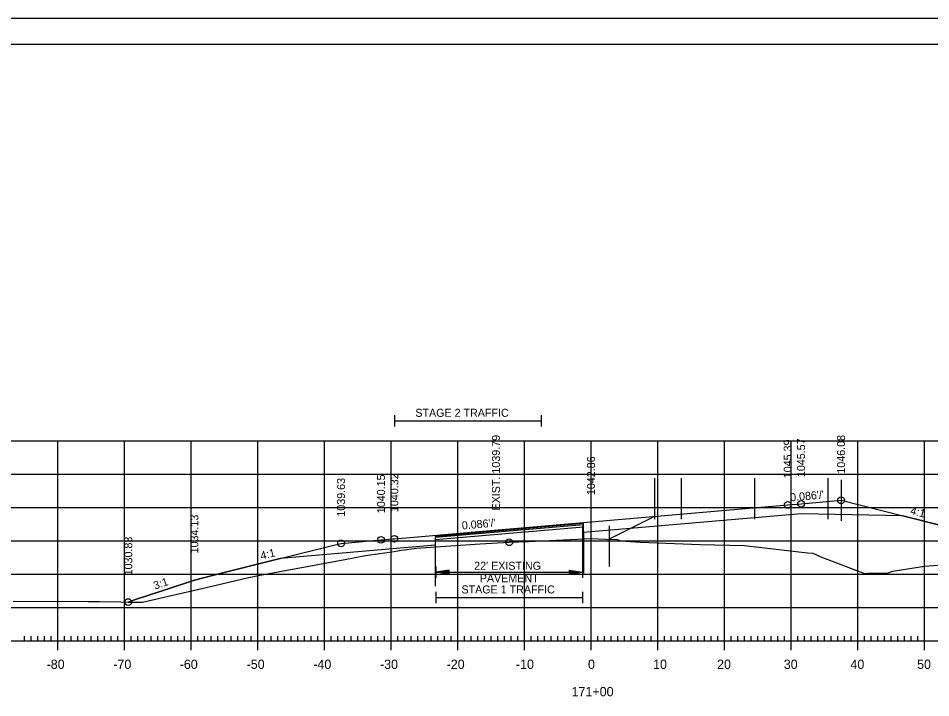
# Model space of a CAD drawing. Extents: x 1322838 to 1324533, y 339903 to 351025.
# Drawn here: x 1323617.8 to 1323754.7, y 347083.3 to 347185.2 of the extents above; entities that cross this region are included whole.
import ezdxf

# ---------------------------------------------------------------- set-up
doc = ezdxf.new("R2010")
doc.units = 0
for name, color, linetype in [('R_Alt Surface', 7, 'Continuous'), ('R_Axis', 7, 'Continuous'), ('R_Axis Annot', 7, 'Continuous'), ('R_Border', 7, 'Continuous'), ('R_Exist Surface', 7, 'Continuous'), ('R_Fin Surface', 7, 'Continuous'), ('R_Fin Surface Annot', 7, 'Continuous'), ('R_Grid', 7, 'Continuous'), ('R_No Plot', 7, 'Continuous'), ('R_Xsect Elev', 7, 'Continuous')]:
    doc.layers.add(name, color=color, linetype=linetype)

msp = doc.modelspace()

# ---------------------------------------------------------------- linework, layer by layer
at = {"layer": 'R_Alt Surface'}
msp.add_lwpolyline([(1323750.5, 347110.6), (1323735.22, 347110.9), (1323703.72, 347108.2), (1323702.59, 347108.09), (1323702.58, 347109.43), (1323680.34, 347107.52), (1323680.33, 347106.18), (1323672.22, 347105.49), (1323657.07, 347104.18)], dxfattribs=at)
at = {"layer": 'R_Axis'}
for p, q in [((1323618.72, 347091.84), (1323618.72, 347092.54)), ((1323619.72, 347091.84), (1323619.72, 347092.54)), ((1323620.72, 347091.84), (1323620.72, 347092.54)), ((1323621.72, 347091.84), (1323621.72, 347092.54)), ((1323622.72, 347091.84), (1323622.72, 347092.54)), ((1323623.72, 347090.44), (1323623.72, 347093.24)), ((1323624.72, 347091.84), (1323624.72, 347092.54)), ((1323625.72, 347091.84), (1323625.72, 347092.54)), ((1323626.72, 347091.84), (1323626.72, 347092.54)), ((1323627.72, 347091.84), (1323627.72, 347092.54)), ((1323628.72, 347091.84), (1323628.72, 347092.54)), ((1323629.72, 347091.84), (1323629.72, 347092.54)), ((1323630.72, 347091.84), (1323630.72, 347092.54)), ((1323631.72, 347091.84), (1323631.72, 347092.54)), ((1323632.72, 347091.84), (1323632.72, 347092.54)), ((1323633.72, 347090.44), (1323633.72, 347093.24)), ((1323634.72, 347091.84), (1323634.72, 347092.54)), ((1323635.72, 347091.84), (1323635.72, 347092.54)), ((1323636.72, 347091.84), (1323636.72, 347092.54)), ((1323637.72, 347091.84), (1323637.72, 347092.54)), ((1323638.72, 347091.84), (1323638.72, 347092.54)), ((1323639.72, 347091.84), (1323639.72, 347092.54)), ((1323640.72, 347091.84), (1323640.72, 347092.54)), ((1323641.72, 347091.84), (1323641.72, 347092.54)), ((1323642.72, 347091.84), (1323642.72, 347092.54)), ((1323643.72, 347090.44), (1323643.72, 347093.24)), ((1323644.72, 347091.84), (1323644.72, 347092.54)), ((1323645.72, 347091.84), (1323645.72, 347092.54)), ((1323646.72, 347091.84), (1323646.72, 347092.54)), ((1323647.72, 347091.84), (1323647.72, 347092.54)), ((1323648.72, 347091.84), (1323648.72, 347092.54)), ((1323649.72, 347091.84), (1323649.72, 347092.54)), ((1323650.72, 347091.84), (1323650.72, 347092.54)), ((1323651.72, 347091.84), (1323651.72, 347092.54)), ((1323652.72, 347091.84), (1323652.72, 347092.54)), ((1323653.72, 347090.44), (1323653.72, 347093.24)), ((1323654.72, 347091.84), (1323654.72, 347092.54)), ((1323655.72, 347091.84), (1323655.72, 347092.54)), ((1323656.72, 347091.84), (1323656.72, 347092.54)), ((1323657.72, 347091.84), (1323657.72, 347092.54)), ((1323658.72, 347091.84), (1323658.72, 347092.54)), ((1323659.72, 347091.84), (1323659.72, 347092.54)), ((1323660.72, 347091.84), (1323660.72, 347092.54)), ((1323661.72, 347091.84), (1323661.72, 347092.54)), ((1323662.72, 347091.84), (1323662.72, 347092.54)), ((1323663.72, 347090.44), (1323663.72, 347093.24)), ((1323664.72, 347091.84), (1323664.72, 347092.54)), ((1323665.72, 347091.84), (1323665.72, 347092.54)), ((1323666.72, 347091.84), (1323666.72, 347092.54)), ((1323667.72, 347091.84), (1323667.72, 347092.54)), ((1323668.72, 347091.84), (1323668.72, 347092.54)), ((1323669.72, 347091.84), (1323669.72, 347092.54)), ((1323670.72, 347091.84), (1323670.72, 347092.54)), ((1323671.72, 347091.84), (1323671.72, 347092.54)), ((1323672.72, 347091.84), (1323672.72, 347092.54)), ((1323673.72, 347090.44), (1323673.72, 347093.24)), ((1323674.72, 347091.84), (1323674.72, 347092.54)), ((1323675.72, 347091.84), (1323675.72, 347092.54)), ((1323676.72, 347091.84), (1323676.72, 347092.54)), ((1323677.72, 347091.84), (1323677.72, 347092.54)), ((1323678.72, 347091.84), (1323678.72, 347092.54)), ((1323679.72, 347091.84), (1323679.72, 347092.54)), ((1323680.72, 347091.84), (1323680.72, 347092.54)), ((1323681.72, 347091.84), (1323681.72, 347092.54)), ((1323682.72, 347091.84), (1323682.72, 347092.54)), ((1323683.72, 347090.44), (1323683.72, 347093.24)), ((1323684.72, 347091.84), (1323684.72, 347092.54)), ((1323685.72, 347091.84), (1323685.72, 347092.54)), ((1323686.72, 347091.84), (1323686.72, 347092.54)), ((1323687.72, 347091.84), (1323687.72, 347092.54)), ((1323688.72, 347091.84), (1323688.72, 347092.54)), ((1323689.72, 347091.84), (1323689.72, 347092.54)), ((1323690.72, 347091.84), (1323690.72, 347092.54)), ((1323691.72, 347091.84), (1323691.72, 347092.54)), ((1323692.72, 347091.84), (1323692.72, 347092.54)), ((1323693.72, 347090.44), (1323693.72, 347093.24)), ((1323694.72, 347091.84), (1323694.72, 347092.54)), ((1323695.72, 347091.84), (1323695.72, 347092.54)), ((1323696.72, 347091.84), (1323696.72, 347092.54)), ((1323697.72, 347091.84), (1323697.72, 347092.54)), ((1323698.72, 347091.84), (1323698.72, 347092.54)), ((1323699.72, 347091.84), (1323699.72, 347092.54)), ((1323700.72, 347091.84), (1323700.72, 347092.54)), ((1323701.72, 347091.84), (1323701.72, 347092.54)), ((1323702.72, 347091.84), (1323702.72, 347092.54)), ((1323703.72, 347090.44), (1323703.72, 347093.24)), ((1323704.72, 347091.84), (1323704.72, 347092.54)), ((1323705.72, 347091.84), (1323705.72, 347092.54)), ((1323706.72, 347091.84), (1323706.72, 347092.54)), ((1323707.72, 347091.84), (1323707.72, 347092.54)), ((1323708.72, 347091.84), (1323708.72, 347092.54)), ((1323709.72, 347091.84), (1323709.72, 347092.54)), ((1323710.72, 347091.84), (1323710.72, 347092.54)), ((1323711.72, 347091.84), (1323711.72, 347092.54)), ((1323712.72, 347091.84), (1323712.72, 347092.54)), ((1323713.72, 347090.44), (1323713.72, 347093.24)), ((1323714.72, 347091.84), (1323714.72, 347092.54)), ((1323715.72, 347091.84), (1323715.72, 347092.54)), ((1323716.72, 347091.84), (1323716.72, 347092.54)), ((1323717.72, 347091.84), (1323717.72, 347092.54)), ((1323718.72, 347091.84), (1323718.72, 347092.54)), ((1323719.72, 347091.84), (1323719.72, 347092.54)), ((1323720.72, 347091.84), (1323720.72, 347092.54)), ((1323721.72, 347091.84), (1323721.72, 347092.54)), ((1323722.72, 347091.84), (1323722.72, 347092.54)), ((1323723.72, 347090.44), (1323723.72, 347093.24)), ((1323724.72, 347091.84), (1323724.72, 347092.54)), ((1323725.72, 347091.84), (1323725.72, 347092.54)), ((1323726.72, 347091.84), (1323726.72, 347092.54)), ((1323727.72, 347091.84), (1323727.72, 347092.54)), ((1323728.72, 347091.84), (1323728.72, 347092.54)), ((1323729.72, 347091.84), (1323729.72, 347092.54)), ((1323730.72, 347091.84), (1323730.72, 347092.54)), ((1323731.72, 347091.84), (1323731.72, 347092.54)), ((1323732.72, 347091.84), (1323732.72, 347092.54)), ((1323733.72, 347090.44), (1323733.72, 347093.24)), ((1323734.72, 347091.84), (1323734.72, 347092.54)), ((1323735.72, 347091.84), (1323735.72, 347092.54)), ((1323736.72, 347091.84), (1323736.72, 347092.54)), ((1323737.72, 347091.84), (1323737.72, 347092.54)), ((1323738.72, 347091.84), (1323738.72, 347092.54)), ((1323739.72, 347091.84), (1323739.72, 347092.54)), ((1323740.72, 347091.84), (1323740.72, 347092.54)), ((1323741.72, 347091.84), (1323741.72, 347092.54)), ((1323742.72, 347091.84), (1323742.72, 347092.54)), ((1323743.72, 347090.44), (1323743.72, 347093.24)), ((1323744.72, 347091.84), (1323744.72, 347092.54)), ((1323745.72, 347091.84), (1323745.72, 347092.54)), ((1323746.72, 347091.84), (1323746.72, 347092.54)), ((1323747.72, 347091.84), (1323747.72, 347092.54)), ((1323748.72, 347091.84), (1323748.72, 347092.54)), ((1323749.72, 347091.84), (1323749.72, 347092.54)), ((1323750.72, 347091.84), (1323750.72, 347092.54)), ((1323751.72, 347091.84), (1323751.72, 347092.54)), ((1323752.72, 347091.84), (1323752.72, 347092.54)), ((1323753.72, 347090.44), (1323753.72, 347093.24)), ((1323563.72, 347091.84), (1323843.72, 347091.84))]:
    msp.add_line(p, q, dxfattribs=at)
at = {"layer": 'R_Axis Annot'}
for p, q in [((1323674.22, 347125.7), (1323674.22, 347124)), ((1323696.22, 347125.7), (1323696.22, 347124)), ((1323674.22, 347124.85), (1323696.22, 347124.85)), ((1323680.46, 347102.99), (1323680.46, 347101.28)), ((1323682.46, 347102.43), (1323680.46, 347102.13)), ((1323682.46, 347101.83), (1323680.46, 347102.13)), ((1323680.46, 347102.13), (1323702.46, 347102.13)), ((1323682.46, 347102.38), (1323680.79, 347102.13)), ((1323682.46, 347101.88), (1323680.79, 347102.13)), ((1323682.46, 347102.33), (1323681.14, 347102.13)), ((1323682.46, 347101.94), (1323681.14, 347102.13)), ((1323682.46, 347102.28), (1323681.47, 347102.13)), ((1323682.46, 347101.99), (1323681.47, 347102.13)), ((1323682.46, 347102.23), (1323681.81, 347102.13)), ((1323682.46, 347102.04), (1323681.81, 347102.13)), ((1323682.46, 347102.18), (1323682.14, 347102.13)), ((1323682.46, 347102.09), (1323682.14, 347102.13)), ((1323682.46, 347101.83), (1323682.46, 347102.43)), ((1323700.46, 347102.43), (1323702.46, 347102.13)), ((1323700.46, 347102.43), (1323700.46, 347101.83)), ((1323700.46, 347102.38), (1323702.13, 347102.13)), ((1323700.46, 347102.33), (1323701.78, 347102.13)), ((1323700.46, 347102.28), (1323701.45, 347102.13)), ((1323700.46, 347102.23), (1323701.11, 347102.13)), ((1323700.46, 347102.18), (1323700.78, 347102.13)), ((1323700.46, 347101.83), (1323702.46, 347102.13)), ((1323700.46, 347102.04), (1323701.11, 347102.13)), ((1323700.46, 347101.94), (1323701.78, 347102.13)), ((1323700.46, 347101.88), (1323702.13, 347102.13)), ((1323700.46, 347101.99), (1323701.45, 347102.13)), ((1323700.46, 347102.09), (1323700.78, 347102.13)), ((1323702.46, 347102.99), (1323702.46, 347101.28)), ((1323680.46, 347099.22), (1323680.46, 347097.52)), ((1323680.46, 347098.37), (1323702.46, 347098.37)), ((1323702.46, 347099.22), (1323702.46, 347097.52))]:
    msp.add_line(p, q, dxfattribs=at)
at = {"layer": 'R_Border'}
for p, q in [((1323545.72, 347181.3), (1323861.9, 347181.3)), ((1323698.24, 347181.04), (1323698.24, 347181.04)), ((1323698.24, 347181.04), (1323698.24, 347181.04))]:
    msp.add_line(p, q, dxfattribs=at)
at = {"layer": 'R_Exist Surface'}
msp.add_lwpolyline([(1323617.06, 347097.79), (1323628.3, 347097.73), (1323630, 347097.73), (1323636.46, 347097.64), (1323645.98, 347099.86), (1323652.15, 347101.3), (1323654.08, 347101.7), (1323666.81, 347104.06), (1323669.9, 347104.64), (1323674.19, 347105.27), (1323674.98, 347105.41), (1323677.55, 347105.74), (1323678.21, 347105.82), (1323687.09, 347106.38), (1323691.46, 347106.63), (1323694.36, 347106.75), (1323703.77, 347107.18), (1323705.96, 347107.09), (1323707.65, 347107.04), (1323708.19, 347106.84), (1323711.1, 347106.63), (1323720.08, 347106.29), (1323726.72, 347106.14), (1323736.2, 347105.07), (1323736.97, 347105.02), (1323738.18, 347104.45), (1323744.75, 347101.94), (1323745.17, 347101.98), (1323748.15, 347101.99), (1323748.99, 347102.31), (1323753.73, 347103.06), (1323760.58, 347103.57)], dxfattribs=at)
at = {"layer": 'R_Fin Surface'}
msp.add_lwpolyline([(1323634.31, 347097.67), (1323635.26, 347097.98), (1323639.7, 347099.47), (1323644.22, 347100.97), (1323648.47, 347102.03), (1323657.07, 347104.18), (1323665.34, 347106.25), (1323666.22, 347106.47), (1323671.07, 347106.89), (1323672.22, 347106.99), (1323673.92, 347107.13), (1323674.22, 347107.16), (1323689.79, 347108.5), (1323703.72, 347109.7), (1323733.22, 347112.23), (1323735.22, 347112.4), (1323741.22, 347112.92), (1323750.5, 347110.6), (1323757.03, 347108.97)], dxfattribs=at)
at = {"layer": 'R_Grid'}
for p, q in [((1323563.72, 347121.84), (1323843.72, 347121.84)), ((1323623.72, 347091.84), (1323623.72, 347121.84)), ((1323633.72, 347091.84), (1323633.72, 347121.84)), ((1323643.72, 347091.84), (1323643.72, 347121.84)), ((1323653.72, 347091.84), (1323653.72, 347121.84)), ((1323663.72, 347091.84), (1323663.72, 347121.84)), ((1323673.72, 347091.84), (1323673.72, 347121.84)), ((1323683.72, 347091.84), (1323683.72, 347121.84)), ((1323693.72, 347091.84), (1323693.72, 347121.84)), ((1323703.72, 347091.84), (1323703.72, 347121.84)), ((1323713.72, 347091.84), (1323713.72, 347121.84)), ((1323723.72, 347091.84), (1323723.72, 347121.84)), ((1323733.72, 347091.84), (1323733.72, 347121.84)), ((1323743.72, 347091.84), (1323743.72, 347121.84)), ((1323753.72, 347091.84), (1323753.72, 347121.84)), ((1323563.72, 347116.84), (1323843.72, 347116.84)), ((1323563.72, 347111.84), (1323843.72, 347111.84)), ((1323563.72, 347106.84), (1323843.72, 347106.84)), ((1323563.72, 347101.84), (1323843.72, 347101.84)), ((1323563.72, 347096.84), (1323843.72, 347096.84)), ((1323563.72, 347091.84), (1323843.72, 347091.84))]:
    msp.add_line(p, q, dxfattribs=at)
at = {"layer": 'R_No Plot'}
for p, q in [((1323533.31, 347185.19), (1323866.65, 347185.19)), ((1323713.22, 347116.23), (1323713.22, 347110.12)), ((1323717.22, 347116.23), (1323717.22, 347110.12)), ((1323728.22, 347116.23), (1323728.22, 347110.12)), ((1323739.22, 347116.23), (1323739.22, 347110.12)), ((1323741.22, 347115.98), (1323741.22, 347109.87)), ((1323713.22, 347110.51), (1323706.44, 347107.12)), ((1323702.61, 347108.89), (1323680.38, 347106.98)), ((1323702.46, 347109.1), (1323702.46, 347102.99)), ((1323706.46, 347109.1), (1323706.46, 347102.99)), ((1323702.59, 347108.09), (1323702.59, 347101.98)), ((1323680.33, 347106.18), (1323680.33, 347100.07))]:
    msp.add_line(p, q, dxfattribs=at)
for points in [[(1323533.31, 347185.19), (1323866.65, 347185.19), (1323866.65, 346971.86), (1323533.31, 346971.86)], [(1323779.64, 347181.3), (1323799.26, 347181.3), (1323799.26, 347171.42), (1323815.37, 347171.42), (1323838.57, 347171.42), (1323838.57, 347138.75), (1323861.77, 347138.75), (1323861.9, 346975.84), (1323545.72, 346975.84), (1323545.72, 347181.3)]]:
    msp.add_lwpolyline(points, close=True, dxfattribs=at)
for points in [[(1323757.03, 347108.97), (1323750.5, 347110.6), (1323735.22, 347110.9), (1323703.72, 347108.2), (1323702.59, 347108.09), (1323702.58, 347109.43), (1323680.34, 347107.52), (1323680.33, 347106.18), (1323672.22, 347105.49), (1323657.07, 347104.18), (1323648.47, 347102.03), (1323644.22, 347100.97), (1323639.7, 347099.47), (1323635.26, 347097.98), (1323634.31, 347097.67), (1323634.31, 347097.67), (1323636.46, 347097.64), (1323645.98, 347099.86), (1323652.15, 347101.3), (1323654.08, 347101.7), (1323666.81, 347104.06), (1323669.9, 347104.64), (1323674.19, 347105.27), (1323674.98, 347105.41), (1323677.55, 347105.74), (1323678.21, 347105.82), (1323687.09, 347106.38), (1323691.46, 347106.63), (1323694.36, 347106.75), (1323703.77, 347107.18), (1323705.96, 347107.09), (1323707.65, 347107.04), (1323708.19, 347106.84), (1323711.1, 347106.63), (1323720.08, 347106.29), (1323726.72, 347106.14), (1323736.2, 347105.07), (1323736.97, 347105.02), (1323738.18, 347104.45), (1323744.75, 347101.94), (1323745.17, 347101.98), (1323748.15, 347101.99), (1323748.99, 347102.31), (1323753.73, 347103.06), (1323760.58, 347103.57)], [(1323702.58, 347109.26), (1323680.34, 347107.35)]]:
    msp.add_lwpolyline(points, dxfattribs=at)
for centre in [(1323741.22, 347112.92), (1323733.22, 347112.23), (1323735.22, 347112.4), (1323674.22, 347107.16), (1323666.22, 347106.47), (1323672.22, 347106.99), (1323691.46, 347106.63), (1323634.31, 347097.67)]:
    msp.add_circle(centre, 0.5, dxfattribs=at)

# ---------------------------------------------------------------- texts
at = {"layer": 'R_Axis Annot'}
for s, height, p in [('STAGE 2 TRAFFIC', 1.2, (1323677.37, 347125.44)), ("22' EXISTING ", 1.2, (1323686.19, 347102.51)), ('PAVEMENT', 1.2, (1323687.04, 347100.64)), ('STAGE 1 TRAFFIC', 1.2, (1323684.29, 347098.96)), ('-80', 1.4, (1323622.06, 347087.64)), ('-70', 1.4, (1323632.06, 347087.64)), ('-60', 1.4, (1323642.02, 347087.64)), ('-50', 1.4, (1323652.06, 347087.64)), ('-40', 1.4, (1323662.06, 347087.64)), ('-30', 1.4, (1323672.06, 347087.64)), ('-20', 1.4, (1323682.06, 347087.64)), ('-10', 1.4, (1323692.45, 347087.64)), ('0', 1.4, (1323703.26, 347087.64)), ('10', 1.4, (1323713.03, 347087.64)), ('20', 1.4, (1323722.63, 347087.64)), ('30', 1.4, (1323732.63, 347087.64)), ('40', 1.4, (1323742.63, 347087.64)), ('50', 1.4, (1323752.63, 347087.64)), ('171+00', 1.4, (1323700.8, 347083.54))]:
    msp.add_text(s, height=height, dxfattribs=at).set_placement(p)
at = {"layer": 'R_Fin Surface Annot'}
for s, rotation, p in [('1046.08', 90, (1323741.82, 347116.92)), ('1045.39', 90, (1323733.82, 347116.23)), ('1045.57', 90, (1323735.82, 347116.4)), ('1042.86', 90, (1323704.32, 347113.7)), ('1039.63', 90, (1323666.82, 347110.47)), ('1040.15', 90, (1323672.82, 347110.99)), ('1040.32', 90, (1323674.82, 347111.16)), ("0.086'/'", 4.9154, (1323733.64, 347112.77)), ('4:1', 345.9637, (1323751.53, 347110.86)), ('1034.13', 90, (1323644.82, 347104.97)), ("0.086'/'", 4.9153, (1323684.39, 347108.54)), ('1030.83', 90, (1323634.91, 347101.67)), ('1030.83', 90, (1323634.91, 347101.67)), ('4:1', 14.0364, (1323654.29, 347104)), ('3:1', 18.433, (1323638.31, 347099.53))]:
    msp.add_text(s, height=1.2, rotation=rotation, dxfattribs=at).set_placement(p)
at = {"layer": 'R_Xsect Elev'}
msp.add_text('EXIST. 1039.79', height=1.2, rotation=90, dxfattribs=at).set_placement((1323690.06, 347111.4))

doc.saveas('drawing.dxf')
